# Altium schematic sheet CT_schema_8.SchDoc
size 254 x 194 mm
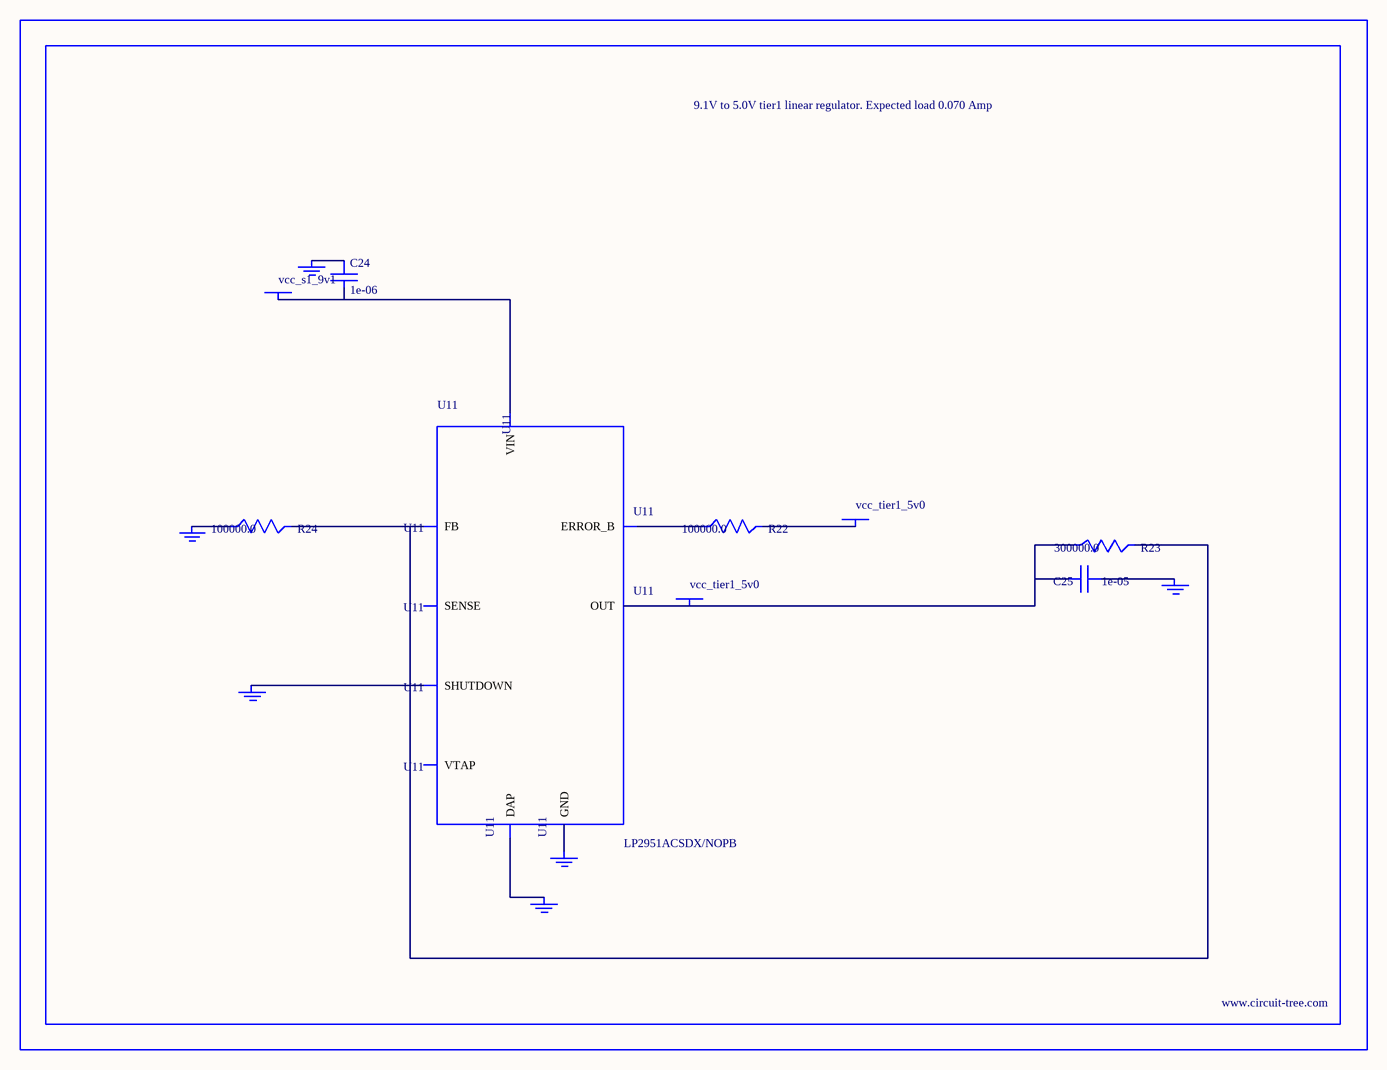
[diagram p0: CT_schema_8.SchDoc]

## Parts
BORDER7  (no value)
C24  1e-06  [C0603]
C25  1e-05  [C1210]
GND_INSTANCE_7_0  (no value)
GND_INSTANCE_7_1  (no value)
GND_INSTANCE_7_2  (no value)
GND_INSTANCE_7_3  (no value)
GND_INSTANCE_7_4  (no value)
GND_INSTANCE_7_5  (no value)
POWER_INSTANCE_7_0  vcc_tier1_5v0
POWER_INSTANCE_7_1  vcc_s1_9v1
POWER_INSTANCE_7_2  vcc_tier1_5v0
R22  100000.0  [R0603]
R23  300000.0  [R0603]
R24  100000.0  [R0603]
U11  LP2951ACSDX/NOPB  [WSON-8]

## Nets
NetC24_1: C24.1 GND_INSTANCE_7_3.0(GND)
NetC24_2: C24.2 POWER_INSTANCE_7_1.0(PWR) U11.8(VIN)
NetC25_1: C25.1 GND_INSTANCE_7_0.0(GND)
NetC25_2: C25.2 POWER_INSTANCE_7_2.0(PWR) R23.1 U11.1(OUT)
NetGND_INSTANCE_7_1_0: GND_INSTANCE_7_1.0(GND) U11.3(SHUTDOWN)
NetGND_INSTANCE_7_2_0: GND_INSTANCE_7_2.0(GND) R24.1
NetGND_INSTANCE_7_4_0: GND_INSTANCE_7_4.0(GND) U11.PAD(DAP)
NetGND_INSTANCE_7_5_0: GND_INSTANCE_7_5.0(GND) U11.4(GND)
NetPOWER_INSTANCE_7_0_0: POWER_INSTANCE_7_0.0(PWR) R22.2
NetR22_1: R22.1 U11.5(ERROR_B)
NetR23_2: R23.2 R24.2 U11.7(FB)

Not connected (* = marked no-connect by the designer): U11 2(SENSE) 6(VTAP)

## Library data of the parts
BORDER7 = BORDER_PAGE7
C24 = C0603C105K3RACTU
C25 = GRM32DR61E106MA12L
GND_INSTANCE_7_0-GND_INSTANCE_7_5 = GND
POWER_INSTANCE_7_0-POWER_INSTANCE_7_2 = PWR
R22 R24 = RC0603JR-07100KL
R23 = RC0603JR-07300KL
